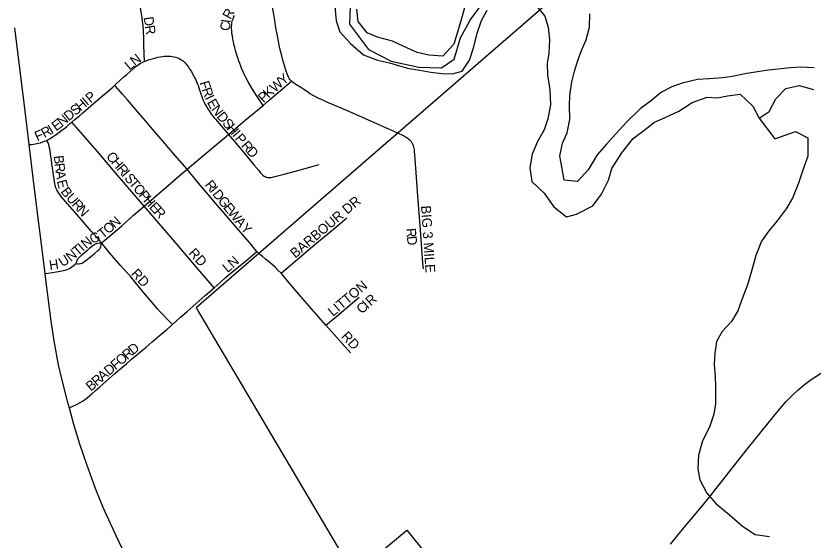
# Model space of a CAD drawing. Extents: x 1451455 to 1749751, y 218250 to 574981.
# Drawn here: x 1605068 to 1609155, y 245182 to 247868 of the extents above; entities that cross this region are included whole.
import ezdxf

# ---------------------------------------------------------------- set-up
doc = ezdxf.new("R2010")
doc.units = 0
for name, color, linetype in [('GM_X_City_Street', 7, 'Continuous'), ('GM_X_City_Street_Text', 7, 'Continuous'), ('GM_X_Corporation', 7, 'Continuous'), ('GM_X_Minor_River', 7, 'Continuous'), ('GM_X_State_Route', 7, 'Continuous'), ('GM_X_US_Route', 7, 'Continuous')]:
    doc.layers.add(name, color=color, linetype=linetype)

msp = doc.modelspace()

# ---------------------------------------------------------------- linework, layer by layer
at = {"layer": 'GM_X_City_Street'}
for points in [[(1605727, 247634.3), (1605724, 247718.7), (1605723.5, 247753.9), (1605721.8, 247790.7), (1605720, 247819), (1605717.4, 247840.7), (1605714.8, 247858.9), (1605712.3, 247876.8), (1605708.8, 247899.3), (1605704.8, 247925.3), (1605700.1, 247960.9), (1605693.2, 248008.3)], [(1606480.9, 247533.3), (1606476.7, 247537.2), (1606472.5, 247542.4), (1606469.4, 247547.2), (1606465.8, 247553.6), (1606462, 247562.4), (1606458.3, 247571.7), (1606453.7, 247584.9), (1606450.3, 247597.1), (1606443.3, 247619.2), (1606436.8, 247641.8), (1606431.2, 247662.6), (1606426, 247681.3), (1606421.6, 247700), (1606417.3, 247718.6), (1606413.4, 247738.2), (1606408.3, 247765.2), (1606401.2, 247807.2), (1606394.7, 247844.5), (1606387.8, 247885.7), (1606385.6, 247902.2), (1606384.5, 247914), (1606384.7, 247920), (1606385.6, 247928.1)], [(1606334.8, 247409.3), (1606300.9, 247460.3), (1606276.6, 247498.1), (1606258, 247529.4), (1606245.8, 247552.4), (1606239.3, 247566.7), (1606232.8, 247581.4), (1606225, 247599.2), (1606220.6, 247611), (1606215.4, 247624.4), (1606209.8, 247640.9), (1606204.1, 247657.8), (1606199, 247673.9), (1606194.2, 247689.9), (1606189.8, 247706.4), (1606185.9, 247721.6), (1606183.3, 247734.2), (1606180.3, 247748.6), (1606177.7, 247765), (1606175.5, 247778), (1606174.2, 247791.9), (1606173.8, 247804.1), (1606173.8, 247814.5), (1606174.6, 247824), (1606175.5, 247832.3), (1606177.2, 247842.3), (1606179.4, 247849.7), (1606182.5, 247857.1), (1606185.5, 247864.4), (1606188.1, 247869.2)], [(1605574.1, 247512.2), (1605604.1, 247539.5), (1605621.9, 247555.3), (1605637.1, 247568.3), (1605654, 247583.1), (1605668.8, 247596.1), (1605677.9, 247604.4), (1605684.9, 247610.2), (1605692.2, 247615.6), (1605699.5, 247620.8), (1605707, 247625), (1605714.4, 247628.9), (1605726.9, 247634.3), (1605727, 247634.3)], [(1605727, 247634.3), (1605739.5, 247639.1), (1605753.4, 247643.9), (1605766.5, 247648), (1605780.4, 247651.9), (1605794.6, 247655.6), (1605807.2, 247658.2), (1605818.9, 247659.9), (1605829.8, 247660.8), (1605841.1, 247661.2), (1605849, 247661.4), (1605859.8, 247661), (1605869.3, 247660.1), (1605876.7, 247658.8), (1605887.1, 247656.6), (1605895.8, 247653.6), (1605902.3, 247650.6), (1605908.4, 247647.5), (1605915.3, 247643.4), (1605921.4, 247639.3), (1605926.2, 247635.2), (1605931.3, 247631), (1605935.7, 247626.7), (1605940.6, 247620.9), (1605946.5, 247613), (1605953.5, 247603), (1605960, 247593.8), (1605967.4, 247582.2), (1605973.8, 247571.1), (1605981.8, 247556.4), (1605987.8, 247543.6), (1605993.4, 247531), (1605996.9, 247522.3), (1606001.6, 247510.6), (1606006, 247498.9), (1606011.2, 247483.7), (1606016.4, 247468.9), (1606021.6, 247454.2), (1606026.8, 247439.9), (1606033.4, 247425.4), (1606038.6, 247414.2), (1606044.6, 247403.4), (1606051.6, 247391.7), (1606058.7, 247380.6), (1606067.7, 247368.2), (1606078.1, 247354.8), (1606084.6, 247346.1), (1606091.1, 247337.9), (1606157.1, 247259.7)], [(1605353.8, 247323.2), (1605372.3, 247338.7), (1605391.3, 247354.7), (1605411.4, 247371.7), (1605466, 247418.6), (1605511.7, 247458.1), (1605530.5, 247474.4), (1605564.2, 247503.2), (1605574.1, 247512.2)], [(1605945.1, 247082.1), (1605882.9, 247154.9), (1605802.6, 247248.2), (1605768.3, 247287.3), (1605733.6, 247328.1), (1605698, 247369.8), (1605670.2, 247402.3), (1605639.4, 247438.4), (1605614.2, 247466.6), (1605579.9, 247505.6), (1605574.1, 247512.2)], [(1606334.8, 247409.3), (1606368, 247437.4), (1606437.1, 247496), (1606480.9, 247533.3)], [(1607157.1, 246571.3), (1607154.8, 246600.8), (1607141.6, 246770.7), (1607129.2, 246944), (1607121.4, 247042), (1607114.3, 247134), (1607113, 247155.7), (1607111.7, 247172.6), (1607110.9, 247180.9), (1607109.7, 247189.1), (1607108.3, 247194.7), (1607106.1, 247201.7), (1607103.9, 247207.3), (1607101, 247213.7), (1607098.3, 247218.2), (1607093.9, 247223.8), (1607089.2, 247228.6), (1607084.8, 247232.9), (1607078.3, 247238.2), (1607072.2, 247242.5), (1607065.3, 247246.8), (1607055.7, 247252.5), (1607032.7, 247263.8), (1607006.8, 247275.1), (1606967.2, 247292.8), (1606922, 247312.8), (1606779, 247375.9), (1606658.2, 247428.2), (1606637.6, 247437.2), (1606616.9, 247446.9), (1606602.2, 247454.3), (1606588.7, 247461.7), (1606576.6, 247469), (1606562.2, 247478.6), (1606544.5, 247490.3), (1606528.8, 247500.3), (1606511.5, 247511.6), (1606498.4, 247519.9), (1606489.7, 247526.4), (1606480.9, 247533.3)], [(1606157.1, 247259.7), (1606244, 247332.8), (1606334.8, 247409.3)], [(1605228.1, 247231.2), (1605233.4, 247234.1), (1605243.4, 247239.8), (1605255.6, 247247.6), (1605267.7, 247255.8), (1605281.9, 247266.1), (1605296.8, 247277.1), (1605313.3, 247289.7), (1605328.1, 247301.8), (1605345, 247315.7), (1605353.8, 247323.2)], [(1605724.9, 246893.4), (1605567.8, 247075.5), (1605486.7, 247173.3), (1605353.8, 247323.2)], [(1605134, 247208.4), (1605150.4, 247209.6), (1605166.1, 247212), (1605183.5, 247215.5), (1605194.4, 247218.1), (1605206, 247221.9), (1605215.1, 247225.4), (1605222, 247228.4), (1605228.1, 247231.2)], [(1605506.4, 246704.8), (1605455.5, 246762.3), (1605393.5, 246833.9), (1605310.1, 246930.7), (1605300.1, 246942.4), (1605292.3, 246951.9), (1605287, 246959.2), (1605281.9, 246967.6), (1605277.6, 246975.8), (1605273.2, 246987.1), (1605269.8, 246997.9), (1605267.2, 247008.8), (1605265.4, 247017.9), (1605263.3, 247033.1), (1605261.1, 247050), (1605258, 247069.6), (1605255.5, 247088.2), (1605252.4, 247109.9), (1605249.4, 247131.2), (1605247.2, 247147.2), (1605245, 247162), (1605242.9, 247175.5), (1605241.1, 247185.9), (1605238.9, 247196.3), (1605235.9, 247208), (1605232, 247221.5), (1605228.1, 247231.2)], [(1605945.1, 247082.1), (1605990.6, 247120.6), (1606085.6, 247200), (1606157.1, 247259.7)], [(1606157.1, 247259.7), (1606233.8, 247169), (1606287.7, 247104.4), (1606312.9, 247075.3), (1606322.4, 247064), (1606330.6, 247054.9), (1606335.4, 247050.5), (1606340.2, 247047), (1606345.4, 247044), (1606351.1, 247041.9), (1606356.7, 247040.5), (1606364.1, 247039.7), (1606369.7, 247039.7), (1606376.2, 247040.5), (1606384, 247041.9), (1606395.3, 247044.5), (1606408.8, 247047.9), (1606442.7, 247056.2), (1606500.8, 247071.4), (1606586.6, 247095.8), (1606622.3, 247105.7)], [(1605724.9, 246893.4), (1605775.3, 246936), (1605861.7, 247011.3), (1605914.1, 247055.7), (1605945.1, 247082.1)], [(1606302.8, 246661.2), (1606293, 246672.7), (1606273.9, 246695.7), (1606198.9, 246783.4), (1606091.2, 246908.4), (1605995.7, 247020.8), (1605945.1, 247082.1)], [(1605506.4, 246704.8), (1605523.5, 246719.1), (1605610, 246791.4), (1605671.1, 246846), (1605724.9, 246893.4)], [(1606083.6, 246474.3), (1605999.7, 246572.2), (1605894.2, 246696.3), (1605758.8, 246853.4), (1605724.9, 246893.4)], [(1606427.1, 246549.2), (1606508.9, 246617.1), (1606601, 246695.6), (1606696.9, 246775.3), (1606763.9, 246833)], [(1605377.5, 246598.7), (1605384.9, 246598), (1605391, 246598), (1605399.3, 246599.3), (1605407.1, 246601.5), (1605414.9, 246605.3), (1605426.2, 246613.6), (1605444, 246628.3), (1605458.3, 246639.7), (1605470.9, 246650.1), (1605486.5, 246663.1), (1605492.6, 246668.3), (1605498.2, 246674.4), (1605501.7, 246680.4), (1605503.9, 246686.1), (1605505.2, 246692.2), (1605506.4, 246704.8)], [(1605377.5, 246598.7), (1605378.8, 246605.2), (1605380.1, 246610.9), (1605382.3, 246616.5), (1605384.5, 246620.9), (1605387.1, 246624.8), (1605390.6, 246628.7), (1605396.6, 246634.3), (1605405.7, 246642.6), (1605419.6, 246654.7), (1605434.4, 246667.7), (1605447.4, 246679.5), (1605457.4, 246687.7), (1605465.2, 246693.3), (1605473, 246698.1), (1605480.4, 246701.1), (1605489.5, 246703.3), (1605496.5, 246704.2), (1605506.4, 246704.8)], [(1605870.3, 246286.8), (1605843.1, 246313.9), (1605821.4, 246336.9), (1605807.5, 246352.1), (1605793.6, 246366.9), (1605775.8, 246386.8), (1605754.6, 246412), (1605723.3, 246448.9), (1605656.5, 246530.6), (1605603.1, 246590.8), (1605549.6, 246652.7), (1605506.4, 246704.8)], [(1606083.6, 246474.3), (1606115.4, 246502.4), (1606141.4, 246525.4), (1606171.4, 246550.6), (1606207.4, 246581), (1606263, 246627), (1606290.8, 246650.9), (1606302.8, 246661.2)], [(1606427.1, 246549.2), (1606411.1, 246565.5), (1606397.2, 246579.4), (1606383.7, 246592), (1606362.9, 246609.8), (1606347.3, 246621.9), (1606331.2, 246635), (1606319.1, 246645.4), (1606310.4, 246653.2), (1606302.8, 246661.2)], [(1605215.4, 246547.2), (1605232.1, 246549.7), (1605275.5, 246556.2), (1605296.4, 246559.6), (1605309.4, 246562.3), (1605320.4, 246565), (1605330.6, 246568.7), (1605338.9, 246572.2), (1605345, 246575.3), (1605352.8, 246580.5), (1605363.7, 246588.3), (1605377.5, 246598.7)], [(1606657.6, 246283.2), (1606549.1, 246406.2), (1606467.5, 246502.2), (1606444.1, 246529.5), (1606427.1, 246549.2)], [(1605870.3, 246286.8), (1605910.8, 246323.5), (1605945.7, 246353.6), (1605977.2, 246380.3), (1606037.3, 246434.3), (1606083.6, 246474.3)], [(1606657.6, 246283.2), (1606713.7, 246329), (1606793.2, 246396.6), (1606828.3, 246426.5)], [(1605340.3, 245859.1), (1605359.7, 245867.4), (1605374.2, 245874.1), (1605384.6, 245879.1), (1605397.3, 245885.9), (1605411.8, 245894.8), (1605421.9, 245902.2), (1605432.7, 245910.9), (1605446.1, 245921.7), (1605458.7, 245932.1), (1605474.8, 245946.4), (1605498.2, 245967.3), (1605543.3, 246007.2), (1605576.8, 246037.1), (1605590.7, 246048.9), (1605607.6, 246062.8), (1605634.5, 246084.9), (1605661, 246107.9), (1605687.9, 246130.5), (1605710.5, 246149.1), (1605735.2, 246170), (1605766.9, 246197.3), (1605801.6, 246227.7), (1605840.7, 246261.1), (1605870.3, 246286.8)], [(1606783.5, 246141.9), (1606657.6, 246283.2)]]:
    msp.add_lwpolyline(points, dxfattribs=at)
at = {"layer": 'GM_X_Corporation'}
for points in [[(1606782.6, 247965.7), (1606777.4, 247825.4), (1606876.3, 247696), (1606991.9, 247636.7), (1607133.8, 247605.3), (1607249.9, 247602.2), (1607314.3, 247645.7), (1607347.3, 247755.7), (1607396.2, 247845.5), (1607463, 247937.1)], [(1607809.5, 247945.9), (1605991.7, 246372.4), (1606808.4, 244992.3)], [(1606821.2, 245021.8), (1607071.7, 245232), (1607172.4, 245107.7)]]:
    msp.add_lwpolyline(points, dxfattribs=at)
at = {"layer": 'GM_X_Minor_River'}
for points in [[(1606703.2, 247917.7), (1606710.2, 247843.4), (1606729.3, 247787), (1606782.5, 247726.1), (1606849.7, 247669), (1606921.4, 247641.9), (1606983.2, 247627), (1607074.9, 247599.6), (1607138.9, 247590.6), (1607194.8, 247579.8), (1607250.7, 247573), (1607304.7, 247570.2), (1607355, 247585.5), (1607393.9, 247641.1), (1607414.9, 247709), (1607431.9, 247778.9), (1607454.9, 247844.8), (1607483.7, 247896.5)], [(1607372.1, 247928.2), (1607353, 247854.2), (1607336.2, 247802.4), (1607313, 247722.5), (1607256, 247661.1), (1607184, 247666.2), (1607124.2, 247681.1), (1607052.6, 247712.2), (1606998.9, 247739), (1606921.1, 247758.2), (1606869.4, 247781), (1606822.2, 247839.8), (1606815.1, 247902.1)], [(1607724.5, 247933.1), (1607779.6, 247866.2), (1607796.7, 247809.8), (1607803.8, 247745.5), (1607800.8, 247677.4), (1607792, 247623.4), (1607793.1, 247565.2), (1607806, 247488.8), (1607808.9, 247412.6), (1607795.8, 247340.6), (1607777, 247284.7), (1607742.1, 247225), (1607715.1, 247159.2), (1607702, 247089.2), (1607713, 247018.9), (1607776.2, 246959.8), (1607825.2, 246888.9), (1607890.5, 246837.9), (1607942.8, 246851.2), (1608025.5, 246894.1), (1608070.4, 246953.6), (1608105.5, 247025.3), (1608122.4, 247085.2), (1608173.7, 247166.7), (1608232.8, 247240), (1608287.5, 247281.4), (1608342.1, 247322.7), (1608396.5, 247348), (1608467.1, 247379), (1608535.8, 247424.2), (1608612.3, 247451.1), (1608664.3, 247448.4), (1608716.5, 247457.7), (1608780.7, 247466.8), (1608845.8, 247405.7), (1608879, 247343), (1608929.5, 247378.4), (1608964.5, 247442.1), (1609015.3, 247495.5), (1609083.6, 247510.5), (1609157.4, 247491.4)], [(1609161.1, 247601.7), (1609093, 247604.6), (1609038.9, 247601.4), (1608976.8, 247594.3), (1608924.6, 247589), (1608870.5, 247581.8), (1608804.2, 247570.7), (1608742, 247557.6), (1608689.8, 247550.3), (1608621.7, 247545.3), (1608561.6, 247542.1), (1608483.2, 247523.2), (1608430.9, 247503.9), (1608378.4, 247476.6), (1608321.7, 247431.3), (1608269.1, 247391.9), (1608200, 247324.7), (1608143, 247263.4), (1608096.2, 247209.9), (1608047.4, 247156.5), (1608002.2, 247078.9), (1607947.3, 247019.5), (1607879.3, 247026.5), (1607866.3, 247094.9), (1607857.1, 247149.2), (1607870.1, 247215.2), (1607894.9, 247269), (1607907.9, 247336.9), (1607906.9, 247409.1), (1607907.7, 247459.3), (1607918.7, 247529.3), (1607931.6, 247585.3), (1607948.4, 247639.1), (1607967.2, 247691), (1607992, 247744.8), (1608009, 247810.7), (1608010, 247878.9)], [(1608879, 247343), (1608959.5, 247237.6), (1609064.2, 247276.2), (1609127.7, 247243.2), (1609128.4, 247149), (1609103.4, 247083.1), (1609080.3, 247011.3), (1609049.1, 246933.5), (1609016.3, 246879.9), (1608971.3, 246818.3), (1608928.5, 246766.8), (1608889.7, 246713.2), (1608860.6, 246639.4), (1608839.4, 246559.5), (1608818.4, 246489.6), (1608793.4, 246423.8), (1608768.4, 246356), (1608737.5, 246302.3), (1608688.7, 246250.9), (1608659.9, 246199.1), (1608651.1, 246139.1), (1608648.2, 246083), (1608653.3, 246018.8), (1608654.5, 245966.6), (1608655.3, 245880.4), (1608646.5, 245826.3), (1608623.5, 245760.5), (1608588.4, 245690.8), (1608567.3, 245616.9), (1608564.3, 245546.7), (1608573.5, 245490.5), (1608610.5, 245421.7), (1608657.8, 245366.9), (1608725, 245311.8), (1608792.3, 245252.7), (1608857.7, 245209.6), (1608931.6, 245200.5)]]:
    msp.add_lwpolyline(points, dxfattribs=at)
at = {"layer": 'GM_X_State_Route'}
msp.add_lwpolyline([(1608424.3, 245160.2), (1608501.4, 245254.2), (1608582.8, 245351.6), (1608592.5, 245363.5), (1608597.9, 245370.1), (1608606.6, 245381.1), (1608628.7, 245408.7), (1608658.9, 245446.4), (1608686.9, 245482.4), (1608721.4, 245526.1), (1608816.4, 245647.7), (1608888.6, 245737), (1608975.7, 245843.9), (1609016.9, 245890.9), (1609049, 245924.1), (1609078.1, 245951.1), (1609111.2, 245978.4), (1609145.8, 246003.7), (1609217.2, 246050.9)], dxfattribs=at)
at = {"layer": 'GM_X_US_Route'}
msp.add_lwpolyline([(1605060.3, 247807.1), (1605111.4, 247393.7), (1605134, 247208.4), (1605158.3, 247009.4), (1605215.4, 246547.2), (1605219, 246517.7), (1605246, 246303), (1605261.9, 246202.7), (1605284.9, 246080.3), (1605303.1, 246000.6), (1605331.3, 245892.8), (1605340.3, 245859.1), (1605349, 245826.2), (1605362.7, 245775.7), (1605393.2, 245675.5), (1605429.1, 245570.1), (1605454.6, 245499.4), (1605478.8, 245434.7), (1605514.1, 245350.1), (1605580.7, 245204.5), (1605714.9, 244919)], dxfattribs=at)

# ---------------------------------------------------------------- texts
at = {"layer": 'GM_X_City_Street_Text'}
for s, rotation, p in [('R', 61.9646, (1606168.2, 247846.7)), ('D', 278.1803, (1605722.4, 247860.5)), ('C', 88.8828, (1606166.4, 247791.2)), ('I', 83.2965, (1606167.1, 247829.5)), ('R', 279.3026, (1605728.8, 247815.9)), ('N', 37.9104, (1605677.3, 247609.4)), ('L', 39.3814, (1605650.4, 247587.3)), ('W', 41.2998, (1606395.3, 247473)), ('Y', 38.9316, (1606437.8, 247510.4)), ('F', 288.057, (1606008.8, 247525.7)), ('K', 42.0989, (1606362.8, 247443.6)), ('P', 39.8235, (1605449.8, 247419.4)), ('R', 289.0246, (1606020, 247491.4)), ('P', 42.1009, (1606336.7, 247420)), ('H', 39.8063, (1605399.1, 247377.1)), ('I', 39.8, (1605432.9, 247405.3)), ('I', 295.0711, (1606035.1, 247448.6)), ('E', 298.696, (1606046, 247425.6)), ('D', 39.8123, (1605338.2, 247326.4)), ('S', 39.8082, (1605372, 247354.6)), ('N', 306.6259, (1606067, 247388.4)), ('N', 39.7289, (1605304.3, 247298.3)), ('D', 309.1526, (1606094.7, 247351.2)), ('I', 30.7104, (1605250.2, 247261)), ('E', 36.7957, (1605274, 247275.5)), ('S', 309.998, (1606123, 247316.4)), ('H', 310.1257, (1606145.7, 247289.3)), ('F', 23.1506, (1605176.7, 247224.9)), ('R', 28.7221, (1605213.9, 247241)), ('I', 310.1434, (1606174, 247255.7)), ('P', 310.1383, (1606188.2, 247238.9)), ('R', 310.9346, (1606219.9, 247201.3)), ('D', 312.6267, (1606246.9, 247170.2)), ('B', 277.0847, (1605261.2, 247150)), ('C', 310.0178, (1605527.4, 247146.3)), ('H', 310.03, (1605552.9, 247116)), ('R', 277.0606, (1605266.1, 247110.7)), ('R', 310.0178, (1605581.2, 247082.3)), ('A', 277.081, (1605270.9, 247071.4)), ('I', 310.0319, (1605606.6, 247052)), ('S', 310.0337, (1605620.8, 247035.1)), ('E', 283.261, (1605277.4, 247022)), ('T', 310.0063, (1605643.4, 247008.2)), ('R', 309.1036, (1606033.5, 247001)), ('B', 307.2113, (1605295.1, 246967.2)), ('O', 310.03, (1605666.1, 246981.2)), ('P', 310.0041, (1605694.4, 246947.5)), ('I', 309.1223, (1606058.5, 246970.3)), ('D', 309.1172, (1606072.4, 246953.2)), ('U', 312.149, (1605322.1, 246932)), ('H', 311.3209, (1605717.8, 246919.6)), ('G', 309.0968, (1606100.1, 246919)), ('BARBOUR DR', 40.1262, (1606499.8, 246623.9)), ('R', 312.1014, (1605351.6, 246899.4)), ('N', 312.0837, (1605378.1, 246870)), ('E', 313.0733, (1605748, 246885.3)), ('E', 309.117, (1606127.9, 246884.9)), ('R', 313.1402, (1605772.1, 246859.5)), ('W', 309.0984, (1606150.1, 246857.6)), ('BIG 3 MILE', 273.9725, (1607144.4, 246894.6)), ('N', 41.0543, (1605574.6, 246776)), ('A', 310.3488, (1606186.9, 246812.3)), ('T', 38.9743, (1605512.6, 246723.7)), ('O', 41.0618, (1605541.4, 246747.1)), ('Y', 312.4197, (1606216.7, 246777.3)), ('R', 274.7168, (1607068.2, 246778.4)), ('N', 40.8816, (1605427.5, 246672.9)), ('G', 21.1419, (1605456.9, 246699.4)), ('D', 276.63, (1607071.6, 246737.1)), ('T', 41.1306, (1605384.4, 246635.3)), ('I', 41.1324, (1605410.9, 246658.5)), ('N', 38.8449, (1605348.5, 246606.3)), ('RD', 312.8801, (1605949.5, 246649.5)), ('H', 8.7464, (1605242, 246564.5)), ('U', 32.6651, (1605306.7, 246579.1)), ('N', 41.5942, (1606180.8, 246572.8)), ('RD', 312.8801, (1605654.7, 246543.9)), ('L', 39.6823, (1606152.3, 246549.2)), ('LITTON', 40.2385, (1606693.2, 246324.6)), ('I', 41.4738, (1606870.5, 246363.9)), ('R', 41.4212, (1606887, 246378.5)), ('C', 41.7891, (1606841, 246337.6)), ('RD', 312.8717, (1606732.7, 246222.7)), ('R', 40.8456, (1605638.8, 246103)), ('D', 39.0822, (1605668.4, 246128.6)), ('O', 40.8529, (1605605.5, 246074.2)), ('D', 40.857, (1605545.6, 246022.4)), ('F', 40.8667, (1605578.9, 246051.2)), ('A', 40.863, (1605512.3, 245993.6)), ('B', 40.866, (1605452.4, 245941.8)), ('R', 40.8456, (1605482.4, 245967.7))]:
    msp.add_text(s, height=50, rotation=rotation, dxfattribs=at).set_placement(p)

doc.saveas('drawing.dxf')
